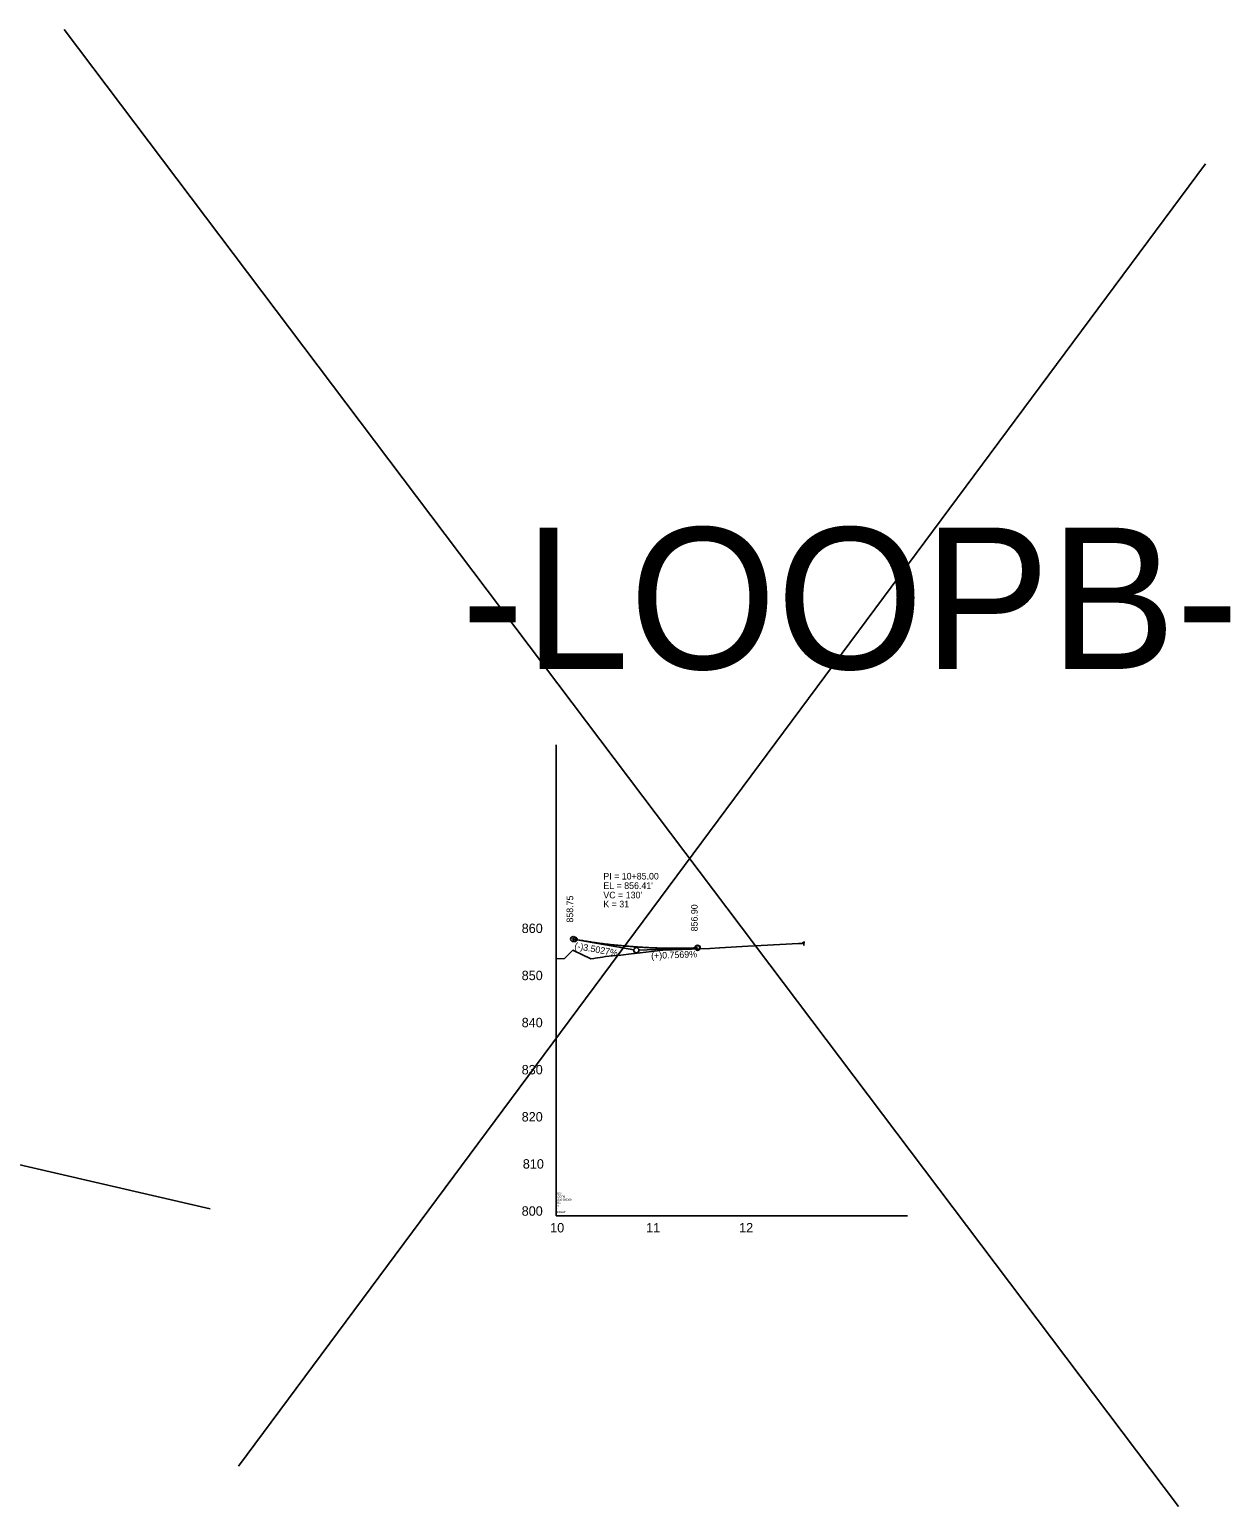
# Model space of a CAD drawing. Extents: x 570622 to 580296, y -55533 to -48575.
# Drawn here: x 576785 to 578059, y -51835 to -50268 of the extents above; entities that cross this region are included whole.
import ezdxf

# ---------------------------------------------------------------- set-up
doc = ezdxf.new("R2010")
doc.units = 0
for name, color, linetype in [('Default', 7, 'Continuous'), ('Exist Profile Cell', 7, 'Continuous'), ('Exist Vertical Profile Ground Line', 7, 'Continuous'), ('Exist Vertical Profile Horizontal Axis Label Major', 7, 'Continuous'), ('Exist Vertical Profile Vertical Axis Label', 7, 'Continuous'), ('Prop Vertical Profile Curve Label', 7, 'Continuous'), ('Prop Vertical Profile Grade', 7, 'Continuous'), ('Prop Vertical Profile Grade Label', 7, 'Continuous'), ('Prop VPI Label', 7, 'Continuous')]:
    doc.layers.add(name, color=color, linetype=linetype)

msp = doc.modelspace()

# ---------------------------------------------------------------- linework, layer by layer
at = {"layer": 'Default'}
for p, q in [((576821.6, -50267.9), (578003.5, -51835.2)), ((577006.7, -51792.5), (578032, -50410.4))]:
    msp.add_line(p, q, dxfattribs=at)
at = {"layer": 'Exist Profile Cell'}
for p, q in [((573874.3, -50801.3), (576976.7, -51519.5)), ((577343.5, -51526.9), (577343.5, -51026.9)), ((577343.5, -51526.9), (577716, -51526.9)), ((577343.5, -51526.9), (577343.5, -51526.9))]:
    msp.add_line(p, q, dxfattribs=at)
at = {"layer": 'Exist Vertical Profile Ground Line'}
msp.add_lwpolyline([(577343.5, -51254.2), (577352.4, -51253.7), (577361.2, -51245), (577361.7, -51245.3), (577380.4, -51254.2), (577383.3, -51253.8), (577384.7, -51253.4), (577392.6, -51252.2), (577395.7, -51251.7), (577403.2, -51251), (577407.7, -51250.6), (577409.2, -51250.6), (577425.7, -51248.5), (577426.6, -51248.5), (577456.6, -51244.8), (577476.6, -51244.1), (577477.1, -51244.1), (577506.3, -51243), (577506.6, -51243), (577516.7, -51242.4), (577517, -51242.4), (577546.8, -51240.7), (577560.8, -51239.9), (577600.6, -51237.9), (577602.3, -51237.9), (577603.7, -51237.8), (577604.1, -51237.7), (577604.8, -51237.7), (577605.5, -51236.4), (577605.9, -51237.1), (577606.2, -51237.8), (577606.2, -51239.7), (577606.5, -51235.8)], dxfattribs=at)
at = {"layer": 'Prop Vertical Profile Curve Label'}
for centre in [(577363.5, -51233.5), (577493.5, -51242.4)]:
    msp.add_circle(centre, 2.25, dxfattribs=at)
at = {"layer": 'Prop Vertical Profile Grade'}
msp.add_line((577361.5, -51233.1), (577363.5, -51233.5), dxfattribs=at)
msp.add_spline([(577363.5, -51233.5), (577366.1, -51233.9), (577368.7, -51234.4), (577371.3, -51234.8), (577373.9, -51235.2), (577376.5, -51235.6), (577379.1, -51236), (577381.7, -51236.4), (577384.3, -51236.8), (577386.9, -51237.1), (577389.5, -51237.5), (577392.1, -51237.8), (577394.7, -51238.2), (577397.3, -51238.5), (577399.9, -51238.8), (577402.5, -51239.1), (577405.1, -51239.4), (577407.7, -51239.6), (577410.3, -51239.9), (577412.9, -51240.1), (577415.5, -51240.4), (577418.1, -51240.6), (577420.7, -51240.8), (577423.3, -51241), (577425.9, -51241.2), (577428.5, -51241.4), (577431.1, -51241.6), (577433.7, -51241.7), (577436.3, -51241.9), (577438.9, -51242), (577441.5, -51242.2), (577444.1, -51242.3), (577446.7, -51242.4), (577449.3, -51242.5), (577451.9, -51242.6), (577454.5, -51242.6), (577457.1, -51242.7), (577459.7, -51242.8), (577462.3, -51242.8), (577464.9, -51242.8), (577467.5, -51242.8), (577470.1, -51242.8), (577472.7, -51242.8), (577475.3, -51242.8), (577477.9, -51242.8), (577480.5, -51242.8), (577483.1, -51242.7), (577485.7, -51242.7), (577488.3, -51242.6), (577490.9, -51242.5), (577493.5, -51242.4)], degree=3, dxfattribs=at)
at = {"layer": 'Prop VPI Label'}
for p, q in [((577363.5, -51233.5), (577425.8, -51244.4)), ((577493.5, -51242.4), (577431.2, -51244.8))]:
    msp.add_line(p, q, dxfattribs=at)
for centre in [(577361.5, -51233.1), (577428.5, -51244.9), (577493.5, -51242.4)]:
    msp.add_circle(centre, 2.75, dxfattribs=at)

# ---------------------------------------------------------------- texts
at = {"layer": 'Default'}
msp.add_text('-LOOPB-', height=150, dxfattribs=at).set_placement((577242.7, -50946.5))
at = {"layer": 'Exist Profile Cell'}
for s, p in [('800', (577343.5, -51513.9)), ('RDY', (577343.5, -51504.2)), ('LOOPB', (577343.5, -51507.4)), ('1000.000000', (577343.5, -51510.7)), ('10', (577343.5, -51517.2)), ('2', (577343.5, -51520.4)), ('NOGAP', (577343.5, -51523.7))]:
    msp.add_text(s, height=2, dxfattribs=at).set_placement(p)
at = {"layer": 'Exist Vertical Profile Horizontal Axis Label Major'}
for s, p in [('10', (577337.1, -51544.4)), ('11', (577438.9, -51544.4)), ('12', (577537.5, -51544.4))]:
    msp.add_text(s, height=10, dxfattribs=at).set_placement(p)
at = {"layer": 'Exist Vertical Profile Vertical Axis Label'}
for s, p in [('860', (577306.9, -51226.7)), ('850', (577306.9, -51276.7)), ('840', (577306.9, -51326.7)), ('830', (577306.9, -51376.7)), ('820', (577306.9, -51426.7)), ('810', (577308.1, -51476.7)), ('800', (577306.9, -51526.7))]:
    msp.add_text(s, height=10, dxfattribs=at).set_placement(p)
at = {"layer": 'Prop Vertical Profile Curve Label'}
for s, p in [("VC = 130'", (577393.5, -51189.9)), ('K = 31', (577393.5, -51199.5))]:
    msp.add_text(s, height=7, dxfattribs=at).set_placement(p)
at = {"layer": 'Prop Vertical Profile Grade Label'}
for s, rotation, p in [('(-)3.5027%', 350.0661, (577362.5, -51243.5)), ('(+)0.7569%', 2.1673, (577444.3, -51254.3))]:
    msp.add_text(s, height=7, rotation=rotation, dxfattribs=at).set_placement(p)
at = {"layer": 'Prop VPI Label'}
for s, p in [('PI = 10+85.00', (577393.5, -51169.9)), ("EL = 856.41'", (577393.5, -51179.9))]:
    msp.add_text(s, height=7, dxfattribs=at).set_placement(p)
for s, p in [('858.75', (577361.5, -51215.6)), ('856.90', (577493.5, -51224.9))]:
    msp.add_text(s, height=7, rotation=90, dxfattribs=at).set_placement(p)

doc.saveas('drawing.dxf')
